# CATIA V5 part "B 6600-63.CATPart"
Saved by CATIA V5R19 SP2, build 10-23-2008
Part number: B 6600-63
Bounding box of the stored display mesh (mm): x -59.975 to 59.975, y -59.975 to 59.975, z 0 to 267
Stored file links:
  C:\Users\Bora\Desktop\3D Katı model\B serisi\B 6600\B 6600-63.CATPart
  C:\Program Files\Dassault Systemes\B19\intel_a\reffiles\standard\MetricThickPitch.txt
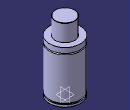
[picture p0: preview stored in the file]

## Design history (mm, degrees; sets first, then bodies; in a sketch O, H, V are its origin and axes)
Body1 (main body)
  Sketch1 on yz-plane, origin (0, 0, 0), H (0, 1, 0), V (0, 0, 1)
    point P3 (37.5, 266)
    point P5 (37.5, 266)
    point P10 (60, 176)
    point P11 (60, 181)
    point P13 (60, 181)
    point P14 (60, 176)
    line L1 (60, 0) -> (60, 8)
    line L2 (37.5, 266) -> (37.5, 201)
    arc A1 centre (36.5, 266) radius 1 from (37.5, 266) to (36.5, 267) ccw
    line L3 (56, 13) -> (56, 8)
    line L4 (60, 13) -> (60, 176)
    line L5 (60, 181) -> (60, 201)
    arc A2 centre (60, 178.5) radius 2.5 from (60, 181) to (60, 176) ccw
    line L6 (36.5, 267) -> (0, 267)
    point P15 (0, 267)
    line L7 (37.5, 201) -> (60, 201)
    line L8 (0, 0) -> (60, 0)
    line L9 (56, 13) -> (60, 13)
    line L10 (56, 8) -> (60, 8)
    tangency: L6 A1
    coincidence: P15 V, P3 P5, P10 P14, P11 P13
    horizontal: L7 H, L8 H, L9 H, L10 H
  Shaft1: profile Sketch1, axis Sketch1.V, angle 360
  Sketch2 on face of Shaft1 from Sketch1.L8, origin (0, 0, 0), H (1, 0, 0), V (0, -1, 0)
    point P1 (40, 0)
    distance P1 V = 40
  Hole1: placed by Sketch2, at (40, 0, 0) direction (0, 0, 1), diameter 8.376, depth 16, threaded "M10", thread diameter 10, thread depth 16, pitch 1.5
  CircPattern1: of Hole1, instances 4, angular step 90, axis from xy-plane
